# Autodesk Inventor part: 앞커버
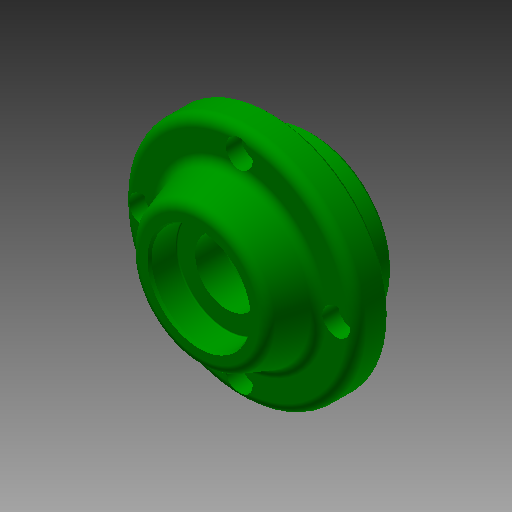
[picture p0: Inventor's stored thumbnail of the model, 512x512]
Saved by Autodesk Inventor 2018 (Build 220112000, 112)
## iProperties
Created: 2017-08
Part Number: 앞커버
Material: 알루미늄 6061
Document SubType Name: Modeling
Designer: mduedu
Density: 2.71 g/cm^3
Appearance: 알루미늄 - 평지
Author: mduedu
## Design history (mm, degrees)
sketch "스케치1"
  geometry: C1 r 35 at (0, 0); 1 further point
  constraints: 1 centre point, 1 coincident
  dimensions: "d0" = 70 diameter of C1
extrude "돌출1" new body sketch "스케치1" distance "d1" = 10; taper "d2" = 0 deg
sketch "스케치2"
  geometry: C1 r 24 at (0, 0); 1 further point
  constraints: 1 centre point, 1 coincident
  dimensions: "d3" = 48 diameter of C1
node "작업 평면1"
sketch "스케치3"
  geometry: C1 r 20 at (0, 0); 1 further point
  constraints: 1 centre point, 1 coincident
  dimensions: "d5" = 40 diameter of C1
feature "로프트1" sketch "스케치3" dims "d6" = 0, "d7" = 90 deg, "d8" = 0, "d9" = 90 deg
sketch "스케치4"
  geometry: C1 r 24 at (0, 0) reference; 1 further point
extrude "돌출2" join sketch "스케치4" distance "d10" = 12; taper "d11" = 0 deg
hole "구멍1" diameter "d14" = 40; stored, may be unused: countersink angle "d18" = 90 deg, drill point angle "d20" = 0 deg; dims "d12" = 10, "d13" = 10, "d15" = 6, "d16" = 4, "d17" = 2, "d19" = 12
hole "구멍2" diameter "d23" = 36; stored, may be unused: countersink angle "d27" = 90 deg, drill point angle "d29" = 0 deg; dims "d24" = 6, "d25" = 4, "d26" = 2, "d28" = 5, "d88" = 10, "d89" = 10
hole "구멍3" diameter "d32" = 19; stored, may be unused: countersink angle "d36" = 90 deg, drill point angle "d38" = 0 deg; dims "d30" = 10, "d31" = 10, "d33" = 6, "d34" = 4, "d35" = 2, "d37" = 3
chamfer "모따기1" distance "d39" = 1; stored, may be unused: second distance "d40" = 2, angle "d41" = 45 deg
sketch "스케치5"
  geometry: C1 r 15 at (0, 0); 1 further point
  constraints: 1 centre point, 1 coincident
  dimensions: "d42" = 30 diameter of C1
extrude "돌출3" cut sketch "스케치5" distance "d43" = 8.3; taper "d44" = 0 deg
chamfer "모따기2" distance "d47" = 0.8; stored, may be unused: second distance "d48" = 2, angle "d49" = 30 deg
fillet "모깎기1" dims "d50" = 0.3
fillet "모깎기2" dims "d51" = 0.3
fillet "모깎기3" dims "d52" = 3
sketch "스케치6" dims "d53" = 66
  geometry: C1 r 24 at (0, 0) reference; C2 r 35 at (0, 0) reference; 6 further points
  constraints: 2 vertical alignment, 1 coincident, 7 other
  dimensions: "d56" = 360 deg dimension on point (0, 0) point (0, 33) (derived)
sketch "스케치9"
  geometry: 4 further points
  constraints: 4 other
hole "구멍6" sketch "스케치9" at (-29, 0), (0, -29), (29, 0), (0, 29) diameter "d72" = 4.5; stored, may be unused: countersink angle "d76" = 90 deg, drill point angle "d78" = 0 deg; dims "d73" = 6, "d74" = 8, "d75" = 4.6, "d77" = 8
fillet "모깎기4" dims "d79" = 3
fillet "모깎기5" dims "d80" = 3
fillet "모깎기6" dims "d81" = 3
chamfer "모따기3" distance "d82" = 1; stored, may be unused: second distance "d83" = 2, angle "d84" = 30 deg
node "솔리드1"
other parameters: "d4" = 12
